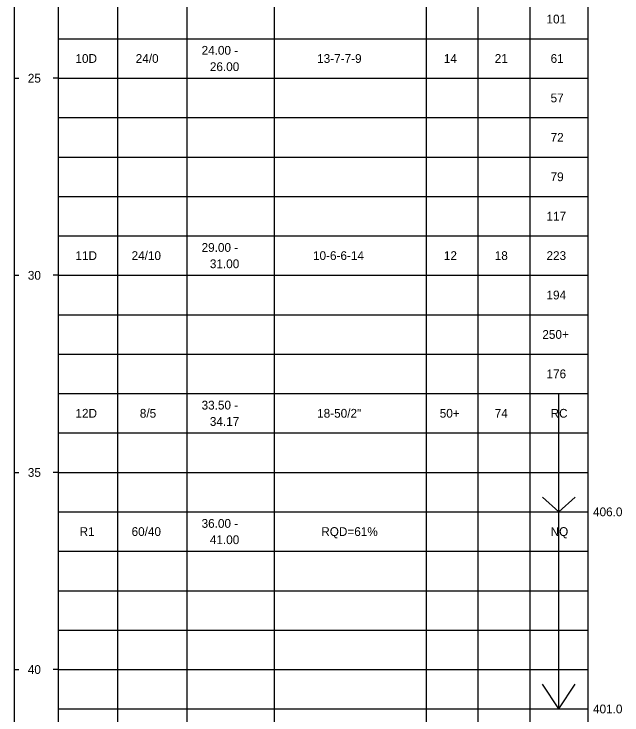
# Model space of a CAD drawing. Extents: x 9422 to 9552, y 6780 to 6860.
# Drawn here: x 9460.28 to 9475.7, y 6805.86 to 6823.64 of the extents above; entities that cross this region are included whole.
import ezdxf

# ---------------------------------------------------------------- set-up
doc = ezdxf.new("R2010")
doc.units = 0
doc.layers.add('7', color=7, linetype='Continuous')

msp = doc.modelspace()

# ---------------------------------------------------------------- linework, layer by layer
at = {"layer": '7'}
for p, q in [((9474.097, 6811.011), (9474.097, 6814.011)), ((9474.097, 6811.011), (9473.68, 6811.386)), ((9474.097, 6811.011), (9474.514, 6811.386)), ((9474.097, 6806.011), (9474.097, 6811.011)), ((9474.097, 6806.011), (9473.68, 6806.636)), ((9474.097, 6806.011), (9474.514, 6806.636))]:
    msp.add_line(p, q, dxfattribs=at)
for points in [[(9460.282, 6860.114), (9460.282, 6821.983)], [(9461.4, 6850.528), (9461.4, 6821.983)], [(9462.909, 6849.992), (9462.909, 6821.983)], [(9464.665, 6849.992), (9464.665, 6821.983)], [(9466.879, 6849.992), (9466.879, 6821.983)], [(9470.734, 6849.992), (9470.734, 6821.983)], [(9472.046, 6849.992), (9472.046, 6821.983)], [(9473.359, 6849.992), (9473.359, 6821.983)], [(9474.835, 6849.992), (9474.835, 6821.983)], [(9461.4, 6823.011), (9462.909, 6823.011)], [(9462.909, 6823.011), (9464.665, 6823.011)], [(9464.665, 6823.011), (9466.879, 6823.011)], [(9466.879, 6823.011), (9470.734, 6823.011)], [(9470.734, 6823.011), (9472.046, 6823.011)], [(9472.046, 6823.011), (9473.359, 6823.011)], [(9473.359, 6823.011), (9474.835, 6823.011)], [(9460.282, 6822.038), (9460.282, 6791.992)], [(9460.282, 6822.011), (9460.404, 6822.011)], [(9461.4, 6822.011), (9461.279, 6822.011)], [(9461.4, 6822.038), (9461.4, 6796.983)], [(9461.4, 6822.011), (9462.909, 6822.011)], [(9462.909, 6822.038), (9462.909, 6796.983)], [(9462.909, 6822.011), (9464.665, 6822.011)], [(9464.665, 6822.038), (9464.665, 6796.983)], [(9464.665, 6822.011), (9466.879, 6822.011)], [(9466.879, 6822.038), (9466.879, 6796.983)], [(9466.879, 6822.011), (9470.734, 6822.011)], [(9470.734, 6822.038), (9470.734, 6796.983)], [(9470.734, 6822.011), (9472.046, 6822.011)], [(9472.046, 6822.038), (9472.046, 6796.983)], [(9472.046, 6822.011), (9473.359, 6822.011)], [(9473.359, 6822.038), (9473.359, 6796.983)], [(9473.359, 6822.011), (9474.835, 6822.011)], [(9474.835, 6822.038), (9474.835, 6796.983)], [(9461.4, 6821.011), (9462.909, 6821.011)], [(9462.909, 6821.011), (9464.665, 6821.011)], [(9464.665, 6821.011), (9466.879, 6821.011)], [(9466.879, 6821.011), (9470.734, 6821.011)], [(9470.734, 6821.011), (9472.046, 6821.011)], [(9472.046, 6821.011), (9473.359, 6821.011)], [(9473.359, 6821.011), (9474.835, 6821.011)], [(9461.4, 6820.011), (9462.909, 6820.011)], [(9462.909, 6820.011), (9464.665, 6820.011)], [(9464.665, 6820.011), (9466.879, 6820.011)], [(9466.879, 6820.011), (9470.734, 6820.011)], [(9470.734, 6820.011), (9472.046, 6820.011)], [(9472.046, 6820.011), (9473.359, 6820.011)], [(9473.359, 6820.011), (9474.835, 6820.011)], [(9461.4, 6819.011), (9462.909, 6819.011)], [(9462.909, 6819.011), (9464.665, 6819.011)], [(9464.665, 6819.011), (9466.879, 6819.011)], [(9466.879, 6819.011), (9470.734, 6819.011)], [(9470.734, 6819.011), (9472.046, 6819.011)], [(9472.046, 6819.011), (9473.359, 6819.011)], [(9473.359, 6819.011), (9474.835, 6819.011)], [(9461.4, 6818.011), (9462.909, 6818.011)], [(9462.909, 6818.011), (9464.665, 6818.011)], [(9464.665, 6818.011), (9466.879, 6818.011)], [(9466.879, 6818.011), (9470.734, 6818.011)], [(9470.734, 6818.011), (9472.046, 6818.011)], [(9472.046, 6818.011), (9473.359, 6818.011)], [(9473.359, 6818.011), (9474.835, 6818.011)], [(9460.282, 6817.011), (9460.404, 6817.011)], [(9461.4, 6817.011), (9461.279, 6817.011)], [(9461.4, 6817.011), (9462.909, 6817.011)], [(9462.909, 6817.011), (9464.665, 6817.011)], [(9464.665, 6817.011), (9466.879, 6817.011)], [(9466.879, 6817.011), (9470.734, 6817.011)], [(9470.734, 6817.011), (9472.046, 6817.011)], [(9472.046, 6817.011), (9473.359, 6817.011)], [(9473.359, 6817.011), (9474.835, 6817.011)], [(9461.4, 6816.011), (9462.909, 6816.011)], [(9462.909, 6816.011), (9464.665, 6816.011)], [(9464.665, 6816.011), (9466.879, 6816.011)], [(9466.879, 6816.011), (9470.734, 6816.011)], [(9470.734, 6816.011), (9472.046, 6816.011)], [(9472.046, 6816.011), (9473.359, 6816.011)], [(9473.359, 6816.011), (9474.835, 6816.011)], [(9461.4, 6815.011), (9462.909, 6815.011)], [(9462.909, 6815.011), (9464.665, 6815.011)], [(9464.665, 6815.011), (9466.879, 6815.011)], [(9466.879, 6815.011), (9470.734, 6815.011)], [(9470.734, 6815.011), (9472.046, 6815.011)], [(9472.046, 6815.011), (9473.359, 6815.011)], [(9473.359, 6815.011), (9474.835, 6815.011)], [(9461.4, 6814.011), (9462.909, 6814.011)], [(9462.909, 6814.011), (9464.665, 6814.011)], [(9464.665, 6814.011), (9466.879, 6814.011)], [(9466.879, 6814.011), (9470.734, 6814.011)], [(9470.734, 6814.011), (9472.046, 6814.011)], [(9472.046, 6814.011), (9473.359, 6814.011)], [(9473.359, 6814.011), (9474.835, 6814.011)], [(9461.4, 6813.011), (9462.909, 6813.011)], [(9462.909, 6813.011), (9464.665, 6813.011)], [(9464.665, 6813.011), (9466.879, 6813.011)], [(9466.879, 6813.011), (9470.734, 6813.011)], [(9470.734, 6813.011), (9472.046, 6813.011)], [(9472.046, 6813.011), (9473.359, 6813.011)], [(9473.359, 6813.011), (9474.835, 6813.011)], [(9460.282, 6812.011), (9460.404, 6812.011)], [(9461.4, 6812.011), (9461.279, 6812.011)], [(9461.4, 6812.011), (9462.909, 6812.011)], [(9462.909, 6812.011), (9464.665, 6812.011)], [(9464.665, 6812.011), (9466.879, 6812.011)], [(9466.879, 6812.011), (9470.734, 6812.011)], [(9470.734, 6812.011), (9472.046, 6812.011)], [(9472.046, 6812.011), (9473.359, 6812.011)], [(9473.359, 6812.011), (9474.835, 6812.011)], [(9461.4, 6811.011), (9462.909, 6811.011)], [(9462.909, 6811.011), (9464.665, 6811.011)], [(9464.665, 6811.011), (9466.879, 6811.011)], [(9466.879, 6811.011), (9470.734, 6811.011)], [(9470.734, 6811.011), (9472.046, 6811.011)], [(9472.046, 6811.011), (9473.359, 6811.011)], [(9473.359, 6811.011), (9474.835, 6811.011)], [(9461.4, 6810.011), (9462.909, 6810.011)], [(9462.909, 6810.011), (9464.665, 6810.011)], [(9464.665, 6810.011), (9466.879, 6810.011)], [(9466.879, 6810.011), (9470.734, 6810.011)], [(9470.734, 6810.011), (9472.046, 6810.011)], [(9472.046, 6810.011), (9473.359, 6810.011)], [(9473.359, 6810.011), (9474.835, 6810.011)], [(9461.4, 6809.011), (9462.909, 6809.011)], [(9462.909, 6809.011), (9464.665, 6809.011)], [(9464.665, 6809.011), (9466.879, 6809.011)], [(9466.879, 6809.011), (9470.734, 6809.011)], [(9470.734, 6809.011), (9472.046, 6809.011)], [(9472.046, 6809.011), (9473.359, 6809.011)], [(9473.359, 6809.011), (9474.835, 6809.011)], [(9461.4, 6808.011), (9462.909, 6808.011)], [(9462.909, 6808.011), (9464.665, 6808.011)], [(9464.665, 6808.011), (9466.879, 6808.011)], [(9466.879, 6808.011), (9470.734, 6808.011)], [(9470.734, 6808.011), (9472.046, 6808.011)], [(9472.046, 6808.011), (9473.359, 6808.011)], [(9473.359, 6808.011), (9474.835, 6808.011)], [(9460.282, 6807.011), (9460.404, 6807.011)], [(9461.4, 6807.011), (9461.279, 6807.011)], [(9461.4, 6807.011), (9462.909, 6807.011)], [(9462.909, 6807.011), (9464.665, 6807.011)], [(9464.665, 6807.011), (9466.879, 6807.011)], [(9466.879, 6807.011), (9470.734, 6807.011)], [(9470.734, 6807.011), (9472.046, 6807.011)], [(9472.046, 6807.011), (9473.359, 6807.011)], [(9473.359, 6807.011), (9474.835, 6807.011)], [(9461.4, 6806.011), (9462.909, 6806.011)], [(9462.909, 6806.011), (9464.665, 6806.011)], [(9464.665, 6806.011), (9466.879, 6806.011)], [(9466.879, 6806.011), (9470.734, 6806.011)], [(9470.734, 6806.011), (9472.046, 6806.011)], [(9472.046, 6806.011), (9473.359, 6806.011)], [(9473.359, 6806.011), (9474.835, 6806.011)]]:
    msp.add_lwpolyline(points, dxfattribs=at)

# ---------------------------------------------------------------- texts
for s, p in [('101', (9473.783, 6823.399)), ('24.00 -', (9465.038, 6822.606)), ('10D', (9461.84, 6822.399)), ('24/0', (9463.368, 6822.399)), ('13-7-7-9', (9467.968, 6822.399)), ('14', (9471.181, 6822.399)), (' 21', (9472.388, 6822.399)), ('61', (9473.887, 6822.399)), ('26.00', (9465.248, 6822.192)), ('25', (9460.632, 6821.899)), ('57', (9473.887, 6821.399)), ('72', (9473.887, 6820.399)), ('79', (9473.887, 6819.399)), ('117', (9473.783, 6818.399)), ('29.00 -', (9465.038, 6817.606)), ('11D', (9461.84, 6817.399)), ('24/10', (9463.263, 6817.399)), ('10-6-6-14', (9467.863, 6817.399)), ('12', (9471.181, 6817.399)), (' 18', (9472.388, 6817.399)), ('223', (9473.783, 6817.399)), ('31.00', (9465.248, 6817.192)), ('30', (9460.632, 6816.899)), ('194', (9473.783, 6816.399)), ('250+', (9473.678, 6815.399)), ('176', (9473.783, 6814.399)), ('33.50 -', (9465.038, 6813.606)), ('12D', (9461.84, 6813.399)), ('8/5', (9463.472, 6813.399)), ('18-50/2"', (9467.968, 6813.399)), ('50+', (9471.076, 6813.399)), (' 74', (9472.388, 6813.399)), ('RC', (9473.887, 6813.399)), ('34.17', (9465.248, 6813.192)), ('35', (9460.632, 6811.899)), ('406.0', (9474.963, 6810.899)), ('36.00 -', (9465.038, 6810.606)), ('R1', (9461.945, 6810.399)), ('60/40', (9463.263, 6810.399)), ('RQD=61%%%', (9468.073, 6810.399)), ('NQ', (9473.887, 6810.399)), ('41.00', (9465.248, 6810.192)), ('40', (9460.632, 6806.899)), ('401.0', (9474.963, 6805.899))]:
    msp.add_text(s, height=0.2228, dxfattribs=at).set_placement(p)

doc.saveas('drawing.dxf')
